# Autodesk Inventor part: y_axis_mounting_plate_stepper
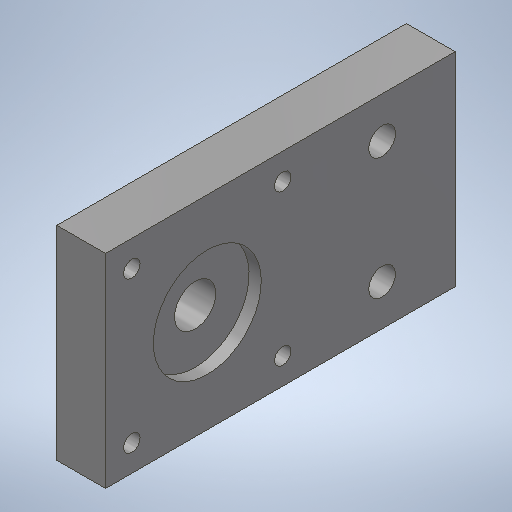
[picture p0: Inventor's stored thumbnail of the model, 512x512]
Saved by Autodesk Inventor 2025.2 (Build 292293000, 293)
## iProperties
Created: 2025-04
Part Number: y_axis_mounting_plate_stepper
Material: 1.0037 S235JR
Document SubType Name: Modeling
Designer: BennF
Density: 7.85 g/cm^3
Appearance: Stahl
Author: BennF
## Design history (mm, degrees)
sketch "Sketch2"
  geometry: L1 (-35.9, -20.9)-(35.9, -20.9); L2 (35.9, -20.9)-(35.9, 20.9); L3 (35.9, 20.9)-(-35.9, 20.9); L4 (-35.9, 20.9)-(-35.9, -20.9); 3 further points
  constraints: 8 end point, 2 midpoint, 2 parallel, 1 horizontal, 1 horizontal alignment, 1 perpendicular, 1 vertical alignment
  dimensions: "d0" = 41.8 distance of L3.end L1.start; "d1" = 71.8 distance of L2.end L3.end (computed from d0)
extrude "Extrusion1" new body sketch "Sketch2" distance "d2" = 10; taper "d3" = 0 deg
sketch "Sketch3"
  geometry: L1 (15.5, 0.5)-(-15.5, 0.5); L2 (-15.5, 0.5)-(-15.5, -30.5); L3 (-15.5, -30.5)-(15.5, -30.5); L4 (15.5, -30.5)-(15.5, 0.5); L5 (20.9, -35.9)-(-20.9, -35.9) reference; 4 further points
  constraints: 8 end point, 2 coincident, 2 parallel, 2 perpendicular, 1 horizontal, 1 midpoint, 1 vertical alignment
  dimensions: "d11" = 31 distance of L3.end L1.start; "d12" = 5.4 distance between parallel lines of L5 L3
hole "Hole1" sketch "Sketch3" at (15.5, -30.5), (15.5, 0.5), (-15.5, 0.5), (-15.5, -30.5) diameter "d4" = 3.4; stored, may be unused: countersink angle "d8" = 90 deg, drill point angle "d10" = 118 deg; dims "d5" = 6, "d6" = 7.5, "d7" = 2, "d9" = 8
workplane "Work Plane1"
sketch "Sketch4"
  geometry: L1 (10, 0)-(10, 41.8) reference; L2 (10, 31.975)-(7.5, 31.975); L3 (7.5, 31.975)-(7.5, 25.15); L4 (7.5, 25.15)-(0, 25.15); L5 (0, 0)-(0, 41.8) reference; L6 (0, 20.9)-(10, 20.9); 1 further point
  constraints: 8 end point, 3 perpendicular, 2 midpoint, 2 point on line, 1 horizontal
  dimensions: "d14" = 22.15 diameter of L2 L6; "d15" = 8.5 diameter of L4 L6; "d16" = 2.5 distance of L2.start L2.end
revolve "Revolution1" sketch "Sketch4" stored, may be unused: angle "d17" = 90 deg
sketch "Sketch5"
  geometry: L1 (12.5, 20.9)-(-12.5, 20.9); L2 (-20.9, 35.9)-(20.9, 35.9) reference; 2 further points
  constraints: 2 end point, 1 horizontal, 1 horizontal alignment, 1 midpoint, 1 vertical alignment
  dimensions: "d25" = 25 distance of L1.start L1.end; "d26" = 15 distance between parallel lines of L1 L2
hole "Hole2" sketch "Sketch5" at (12.5, 20.9), (-12.5, 20.9) diameter "d18" = 5.5; stored, may be unused: countersink angle "d22" = 90 deg, drill point angle "d24" = 118 deg; dims "d19" = 6, "d20" = 12.5, "d21" = 2, "d23" = 8
body "Solid1"
other parameters: "d13" = -20.9 (= -d12 - 0.5 x d11)
